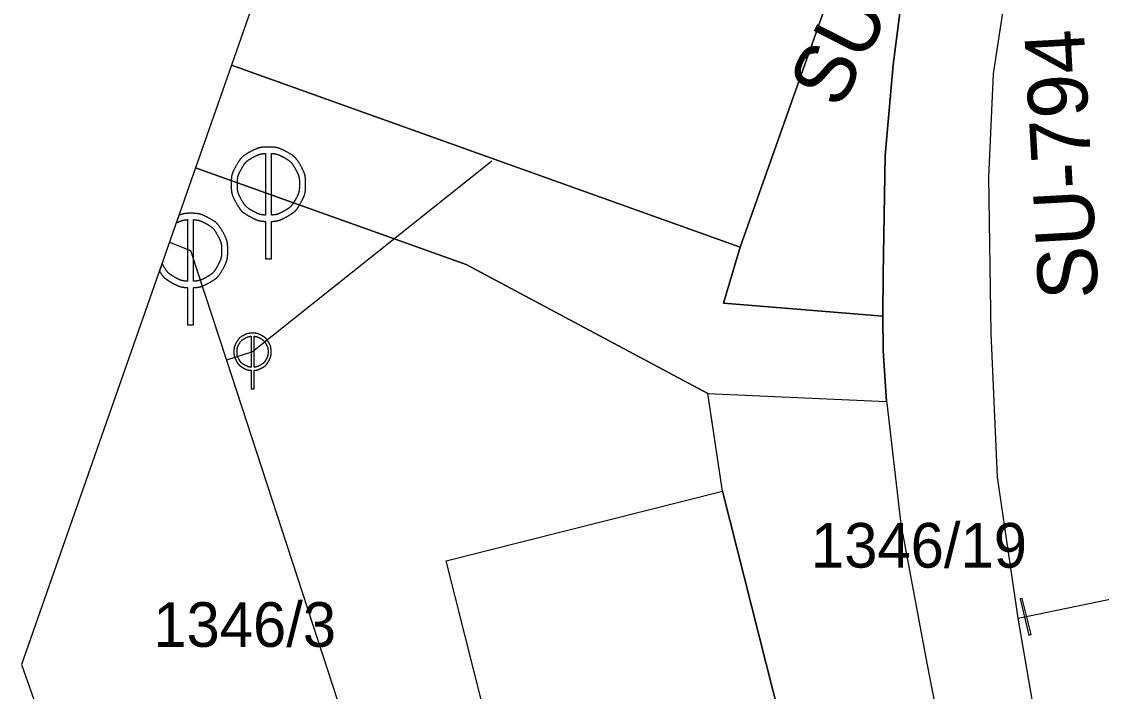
# Model space of a CAD drawing. Extents: x -562248 to -562040, y -1079385 to -1079027.
# Drawn here: x -562161.93 to -562125.69, y -1079124.27 to -1079101.77 of the extents above; entities that cross this region are included whole.
import ezdxf

# ---------------------------------------------------------------- set-up
doc = ezdxf.new("R2010")
doc.units = 0
for name, color, linetype in [('Armatura - popis', 7, 'Continuous'), ('Armatura vodovodní', 7, 'Continuous'), ('Default', 7, 'Continuous'), ('Kanalizační přípojka', 7, 'Continuous'), ('Kanalizační stoka', 7, 'Continuous'), ('Kanalizační šachta', 7, 'Continuous'), ('Parcela-polygon', 7, 'Continuous'), ('Parcela-text', 7, 'Continuous'), ('Vodovodní přípojka', 7, 'Continuous'), ('Vodovodní řad', 7, 'Continuous')]:
    doc.layers.add(name, color=color, linetype=linetype)

msp = doc.modelspace()

# ---------------------------------------------------------------- linework, layer by layer
at = {"layer": 'Armatura vodovodní'}
msp.add_lwpolyline([(-562128.131, -1079122.375), (-562128.055, -1079122.357), (-562128.346, -1079121.141), (-562128.422, -1079121.159)], close=True, dxfattribs=at)
at = {"layer": 'Default'}
for points in [[(-562154.262, -1079106.147), (-562154.46, -1079106.255), (-562154.616, -1079106.409), (-562154.728, -1079106.609)], [(-562154.55, -1079106.715), (-562154.457, -1079106.548), (-562154.328, -1079106.42), (-562154.162, -1079106.33)], [(-562153.647, -1079105.986), (-562153.858, -1079105.986), (-562154.063, -1079106.04), (-562154.262, -1079106.147)], [(-562154.162, -1079106.33), (-562154.019, -1079106.254), (-562153.881, -1079106.21), (-562153.749, -1079106.199)], [(-562153.033, -1079106.147), (-562153.232, -1079106.04), (-562153.437, -1079105.986), (-562153.647, -1079105.986)], [(-562153.544, -1079106.199), (-562153.412, -1079106.21), (-562153.276, -1079106.254), (-562153.134, -1079106.33)], [(-562153.134, -1079106.33), (-562152.968, -1079106.42), (-562152.838, -1079106.548), (-562152.745, -1079106.715)], [(-562152.565, -1079106.609), (-562152.677, -1079106.409), (-562152.833, -1079106.255), (-562153.033, -1079106.147)], [(-562154.728, -1079106.609), (-562154.841, -1079106.809), (-562154.897, -1079107.018), (-562154.897, -1079107.236)], [(-562152.397, -1079107.236), (-562152.397, -1079107.018), (-562152.453, -1079106.809), (-562152.565, -1079106.609)], [(-562154.689, -1079107.236), (-562154.689, -1079107.055), (-562154.643, -1079106.882), (-562154.55, -1079106.715)], [(-562152.745, -1079106.715), (-562152.651, -1079106.882), (-562152.604, -1079107.055), (-562152.604, -1079107.236)], [(-562154.897, -1079107.236), (-562154.897, -1079107.453), (-562154.842, -1079107.66), (-562154.732, -1079107.859)], [(-562154.552, -1079107.754), (-562154.644, -1079107.589), (-562154.689, -1079107.417), (-562154.689, -1079107.236)], [(-562152.604, -1079107.236), (-562152.604, -1079107.417), (-562152.65, -1079107.589), (-562152.741, -1079107.754)], [(-562152.561, -1079107.859), (-562152.452, -1079107.66), (-562152.397, -1079107.453), (-562152.397, -1079107.236)], [(-562154.167, -1079108.137), (-562154.333, -1079108.046), (-562154.461, -1079107.918), (-562154.552, -1079107.754)], [(-562152.741, -1079107.754), (-562152.832, -1079107.918), (-562152.96, -1079108.046), (-562153.124, -1079108.137)], [(-562154.732, -1079107.859), (-562154.622, -1079108.057), (-562154.468, -1079108.211), (-562154.269, -1079108.32)], [(-562153.749, -1079108.271), (-562153.886, -1079108.262), (-562154.025, -1079108.217), (-562154.167, -1079108.137)], [(-562153.124, -1079108.137), (-562153.267, -1079108.217), (-562153.407, -1079108.262), (-562153.544, -1079108.271)], [(-562153.024, -1079108.32), (-562152.826, -1079108.211), (-562152.671, -1079108.057), (-562152.561, -1079107.859)], [(-562154.269, -1079108.32), (-562154.095, -1079108.418), (-562153.922, -1079108.472), (-562153.749, -1079108.484)], [(-562153.544, -1079108.484), (-562153.372, -1079108.472), (-562153.198, -1079108.418), (-562153.024, -1079108.32)], [(-562154.488, -1079112.316), (-562154.587, -1079112.369), (-562154.665, -1079112.446), (-562154.721, -1079112.546)], [(-562154.63, -1079112.599), (-562154.584, -1079112.516), (-562154.519, -1079112.451), (-562154.436, -1079112.406)], [(-562154.18, -1079112.235), (-562154.286, -1079112.235), (-562154.388, -1079112.262), (-562154.488, -1079112.316)], [(-562154.436, -1079112.406), (-562154.365, -1079112.368), (-562154.296, -1079112.346), (-562154.231, -1079112.34)], [(-562153.872, -1079112.316), (-562153.972, -1079112.262), (-562154.074, -1079112.235), (-562154.18, -1079112.235)], [(-562154.129, -1079112.34), (-562154.062, -1079112.346), (-562153.994, -1079112.368), (-562153.924, -1079112.406)], [(-562153.924, -1079112.406), (-562153.841, -1079112.451), (-562153.776, -1079112.516), (-562153.728, -1079112.599)], [(-562153.639, -1079112.546), (-562153.695, -1079112.446), (-562153.773, -1079112.369), (-562153.872, -1079112.316)], [(-562154.721, -1079112.546), (-562154.777, -1079112.646), (-562154.805, -1079112.751), (-562154.805, -1079112.86)], [(-562154.805, -1079112.86), (-562154.805, -1079112.967), (-562154.777, -1079113.071), (-562154.722, -1079113.17)], [(-562154.7, -1079112.86), (-562154.7, -1079112.769), (-562154.677, -1079112.682), (-562154.63, -1079112.599)], [(-562154.632, -1079113.118), (-562154.677, -1079113.035), (-562154.7, -1079112.95), (-562154.7, -1079112.86)], [(-562153.728, -1079112.599), (-562153.681, -1079112.682), (-562153.658, -1079112.769), (-562153.658, -1079112.86)], [(-562153.658, -1079112.86), (-562153.658, -1079112.95), (-562153.68, -1079113.035), (-562153.726, -1079113.118)], [(-562153.555, -1079112.86), (-562153.555, -1079112.751), (-562153.583, -1079112.646), (-562153.639, -1079112.546)], [(-562153.637, -1079113.17), (-562153.582, -1079113.071), (-562153.555, -1079112.967), (-562153.555, -1079112.86)], [(-562154.722, -1079113.17), (-562154.667, -1079113.269), (-562154.589, -1079113.347), (-562154.49, -1079113.402)], [(-562154.439, -1079113.309), (-562154.522, -1079113.264), (-562154.586, -1079113.2), (-562154.632, -1079113.118)], [(-562153.726, -1079113.118), (-562153.771, -1079113.2), (-562153.836, -1079113.264), (-562153.919, -1079113.309)], [(-562153.867, -1079113.402), (-562153.768, -1079113.347), (-562153.691, -1079113.269), (-562153.637, -1079113.17)], [(-562154.49, -1079113.402), (-562154.404, -1079113.451), (-562154.318, -1079113.478), (-562154.231, -1079113.483)], [(-562154.231, -1079113.378), (-562154.3, -1079113.373), (-562154.369, -1079113.35), (-562154.439, -1079113.309)], [(-562153.919, -1079113.309), (-562153.99, -1079113.35), (-562154.06, -1079113.373), (-562154.129, -1079113.378)], [(-562154.129, -1079113.483), (-562154.042, -1079113.478), (-562153.955, -1079113.451), (-562153.867, -1079113.402)]]:
    msp.add_open_spline(points, degree=2, dxfattribs=at)
at = {"layer": 'Kanalizační přípojka'}
msp.add_lwpolyline([(-562146.151, -1079106.464), (-562154.18, -1079112.86), (-562155.056, -1079113.146)], dxfattribs=at)
at = {"layer": 'Kanalizační stoka'}
for points in [[(-562156.967, -1079109.185), (-562156.26, -1079109.46)], [(-562156.26, -1079109.46), (-562155.056, -1079113.146), (-562150.14, -1079128.21), (-562144.91, -1079144.22)]]:
    msp.add_lwpolyline(points, dxfattribs=at)
at = {"layer": 'Kanalizační šachta'}
for p, q in [((-562156.647, -1079108.272), (-562156.739, -1079108.536)), ((-562156.363, -1079108.422), (-562156.363, -1079110.495)), ((-562156.157, -1079110.495), (-562156.157, -1079108.422)), ((-562157.212, -1079109.885), (-562157.305, -1079110.151)), ((-562156.363, -1079110.708), (-562156.363, -1079111.96))]:
    msp.add_line(p, q, dxfattribs=at)
for points in [[(-562153.749, -1079106.199), (-562153.749, -1079108.271)], [(-562153.544, -1079108.271), (-562153.544, -1079106.199)], [(-562153.749, -1079109.736), (-562153.544, -1079109.736), (-562153.544, -1079108.484)], [(-562153.749, -1079108.484), (-562153.749, -1079109.736)], [(-562156.363, -1079111.96), (-562156.157, -1079111.96), (-562156.157, -1079110.708)], [(-562154.231, -1079112.34), (-562154.231, -1079113.378)], [(-562154.129, -1079113.378), (-562154.129, -1079112.34)], [(-562154.231, -1079114.11), (-562154.129, -1079114.11), (-562154.129, -1079113.483)], [(-562154.231, -1079113.483), (-562154.231, -1079114.11)]]:
    msp.add_lwpolyline(points, dxfattribs=at)
for points in [[(-562156.739, -1079108.536), (-562156.609, -1079108.471), (-562156.483, -1079108.433), (-562156.363, -1079108.422)], [(-562156.26, -1079108.21), (-562156.392, -1079108.21), (-562156.521, -1079108.231), (-562156.647, -1079108.272)], [(-562155.646, -1079108.371), (-562155.845, -1079108.264), (-562156.05, -1079108.21), (-562156.26, -1079108.21)], [(-562156.157, -1079108.422), (-562156.026, -1079108.434), (-562155.889, -1079108.478), (-562155.747, -1079108.554)], [(-562155.178, -1079108.833), (-562155.291, -1079108.632), (-562155.447, -1079108.479), (-562155.646, -1079108.371)], [(-562155.747, -1079108.554), (-562155.581, -1079108.644), (-562155.451, -1079108.772), (-562155.358, -1079108.939)], [(-562155.01, -1079109.46), (-562155.01, -1079109.242), (-562155.066, -1079109.033), (-562155.178, -1079108.833)], [(-562155.358, -1079108.939), (-562155.264, -1079109.106), (-562155.218, -1079109.279), (-562155.218, -1079109.46)], [(-562155.218, -1079109.46), (-562155.218, -1079109.641), (-562155.263, -1079109.813), (-562155.354, -1079109.978)], [(-562155.175, -1079110.083), (-562155.065, -1079109.884), (-562155.01, -1079109.676), (-562155.01, -1079109.46)], [(-562157.166, -1079109.978), (-562157.183, -1079109.947), (-562157.198, -1079109.916), (-562157.212, -1079109.885)], [(-562157.305, -1079110.151), (-562157.198, -1079110.317), (-562157.058, -1079110.448), (-562156.883, -1079110.544)], [(-562156.78, -1079110.361), (-562156.946, -1079110.27), (-562157.075, -1079110.142), (-562157.166, -1079109.978)], [(-562155.354, -1079109.978), (-562155.445, -1079110.142), (-562155.573, -1079110.27), (-562155.738, -1079110.361)], [(-562155.637, -1079110.544), (-562155.439, -1079110.435), (-562155.285, -1079110.281), (-562155.175, -1079110.083)], [(-562156.883, -1079110.544), (-562156.708, -1079110.642), (-562156.535, -1079110.696), (-562156.363, -1079110.708)], [(-562156.363, -1079110.495), (-562156.499, -1079110.485), (-562156.638, -1079110.441), (-562156.78, -1079110.361)], [(-562155.738, -1079110.361), (-562155.881, -1079110.441), (-562156.021, -1079110.485), (-562156.157, -1079110.495)], [(-562156.157, -1079110.708), (-562155.985, -1079110.696), (-562155.812, -1079110.642), (-562155.637, -1079110.544)]]:
    msp.add_open_spline(points, degree=2, dxfattribs=at)
at = {"layer": 'Parcela-polygon'}
for p, q in [((-562151.717, -1079094.19), (-562154.883, -1079103.233)), ((-562154.883, -1079103.233), (-562156.09, -1079106.68))]:
    msp.add_line(p, q, dxfattribs=at)
for points in [[(-562151.717, -1079094.19), (-562134.63, -1079100.32), (-562137.81, -1079109.35), (-562138.38, -1079111.23), (-562133.03, -1079111.66), (-562133.02, -1079110.27), (-562132.95, -1079106.27), (-562132.68, -1079103.22), (-562132.29, -1079100.17), (-562131.3, -1079096.35), (-562150.044, -1079089.409)], [(-562154.883, -1079103.233), (-562137.81, -1079109.35), (-562134.63, -1079100.32), (-562151.717, -1079094.19)], [(-562132.29, -1079100.17), (-562132.68, -1079103.22), (-562132.95, -1079106.27), (-562133.02, -1079110.27), (-562133.03, -1079111.66), (-562133.02, -1079112.82), (-562132.9, -1079114.53), (-562132.89, -1079114.59), (-562132.42, -1079118.65), (-562131.55, -1079123.32), (-562130.11, -1079130.72), (-562129.93, -1079133.77), (-562130.82, -1079136.09), (-562133.17, -1079137.64), (-562132.36, -1079140.38), (-562140.21, -1079144.16), (-562153.733, -1079146.647)], [(-562156.09, -1079106.68), (-562147.01, -1079109.93), (-562138.9, -1079114.26), (-562132.9, -1079114.53), (-562133.02, -1079112.82), (-562133.03, -1079111.66), (-562138.38, -1079111.23), (-562137.81, -1079109.35), (-562154.883, -1079103.233)], [(-562156.09, -1079106.68), (-562161.93, -1079123.363), (-562155.326, -1079142.122)], [(-562155.326, -1079142.122), (-562133.17, -1079137.64), (-562134.27, -1079133.92), (-562143.55, -1079136.26), (-562147.68, -1079119.88), (-562138.41, -1079117.54), (-562138.9, -1079114.26), (-562147.01, -1079109.93), (-562156.09, -1079106.68)]]:
    msp.add_lwpolyline(points, dxfattribs=at)
for points in [[(-562130.11, -1079130.72), (-562129.93, -1079133.77), (-562130.82, -1079136.09), (-562133.17, -1079137.64), (-562134.27, -1079133.92), (-562138.41, -1079117.54), (-562138.9, -1079114.26), (-562132.9, -1079114.53), (-562132.89, -1079114.59), (-562132.42, -1079118.65), (-562131.55, -1079123.32)], [(-562147.68, -1079119.88), (-562138.41, -1079117.54), (-562134.27, -1079133.92), (-562143.55, -1079136.26)]]:
    msp.add_lwpolyline(points, close=True, dxfattribs=at)
at = {"layer": 'Vodovodní přípojka'}
msp.add_lwpolyline([(-562128.484, -1079121.808), (-562123.89, -1079120.86), (-562121.868, -1079119.966), (-562108.775, -1079117.222)], dxfattribs=at)
at = {"layer": 'Vodovodní řad'}
msp.add_lwpolyline([(-562104.508, -1079195.68), (-562105.675, -1079193.599), (-562106.045, -1079192.495), (-562108.292, -1079185.845), (-562110.54, -1079179.194), (-562111.609, -1079176.901), (-562113.474, -1079171.283), (-562115.559, -1079165.192), (-562118.308, -1079157.281), (-562119.874, -1079152.505), (-562123.128, -1079142.718), (-562124.818, -1079137.317), (-562126.048, -1079133.176), (-562126.972, -1079129.683), (-562127.886, -1079125.317), (-562128.484, -1079121.808), (-562129.183, -1079117.074), (-562129.389, -1079112.24), (-562129.474, -1079106.997), (-562129.319, -1079103.524), (-562128.819, -1079100.288), (-562128.175, -1079096.35), (-562128.115, -1079096.032)], dxfattribs=at)

# ---------------------------------------------------------------- texts
at = {"layer": 'Armatura - popis'}
for s, rotation, p in [('SU-594', 62.9511, (-562134.473, -1079104.765)), ('SU-794', 93.1344, (-562125.79, -1079111.049))]:
    msp.add_text(s, height=2, rotation=rotation, dxfattribs=at).set_placement(p)
at = {"layer": 'Parcela-text'}
for s, p in [('1346/19', (-562135.44, -1079120.11)), ('1346/3', (-562157.51, -1079122.77))]:
    msp.add_text(s, height=1.5, dxfattribs=at).set_placement(p)

doc.saveas('drawing.dxf')
